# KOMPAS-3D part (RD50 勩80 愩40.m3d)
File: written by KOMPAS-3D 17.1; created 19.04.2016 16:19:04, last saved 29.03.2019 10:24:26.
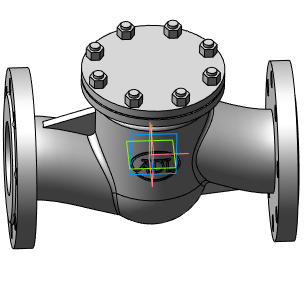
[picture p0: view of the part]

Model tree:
1. Операция без истории:2  (labels: Сталь 20  ГОСТ 1050-88)

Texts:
  RD50 Ду15 Ру40
  RD50 Ду20 Ру40
  RD50 Ду25 Ру40
  RD50 Ду32 Ру40
  RD50 Ду40 Ру40
  RD50 Ду50 Ру40
  RD50 Ду65 Ру40
  RD50 Ду80 Ру40
  RD50 Ду100 Ру40
  RD50 Ду125 Ру40
  RD50 Ду150 Ру40
  RD50 Ду200 Ру40
  RD50 Ду250 Ру40
  RD50 Ду300 Ру40
  RD50 Ду350 Ру40
  RD50 Ду400 Ру40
